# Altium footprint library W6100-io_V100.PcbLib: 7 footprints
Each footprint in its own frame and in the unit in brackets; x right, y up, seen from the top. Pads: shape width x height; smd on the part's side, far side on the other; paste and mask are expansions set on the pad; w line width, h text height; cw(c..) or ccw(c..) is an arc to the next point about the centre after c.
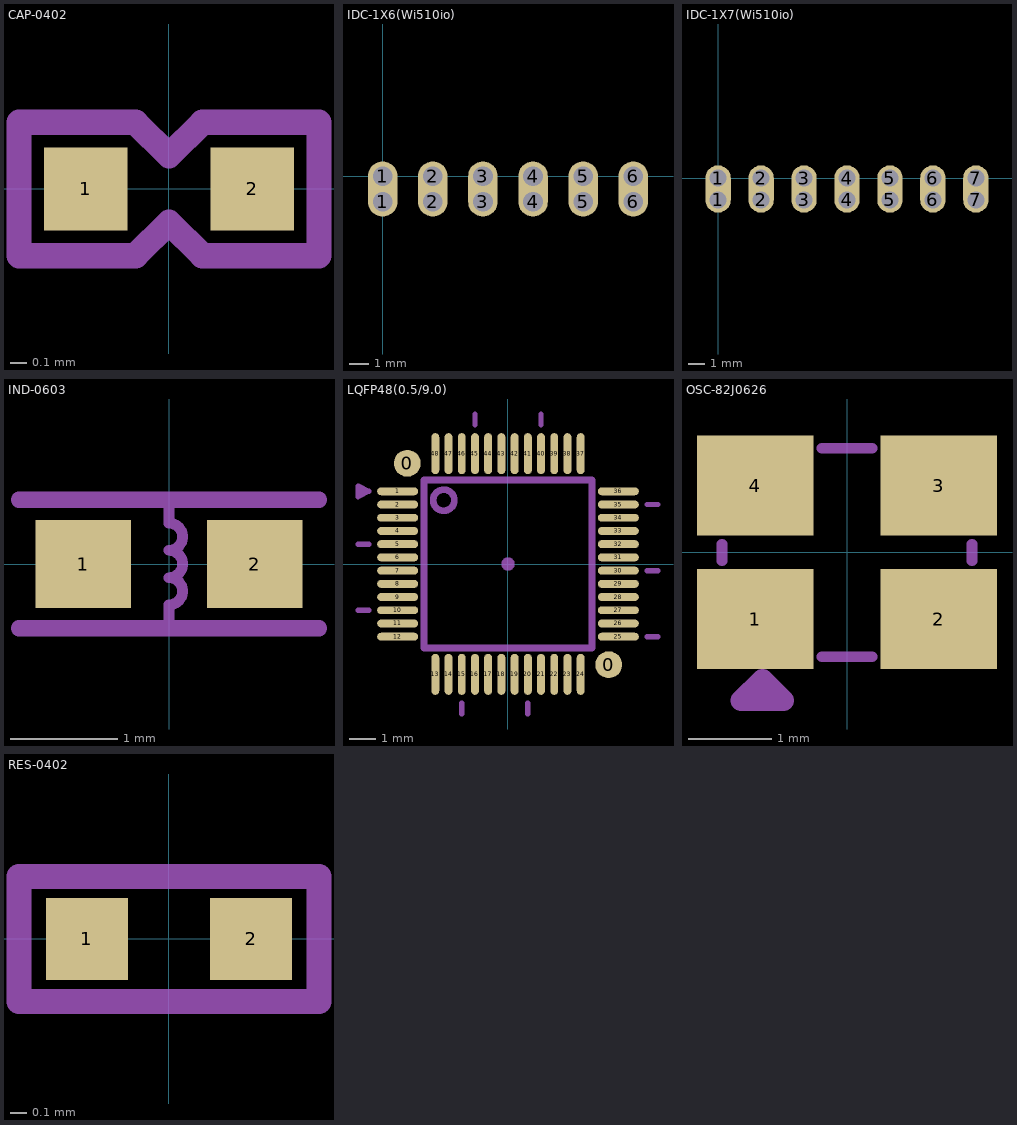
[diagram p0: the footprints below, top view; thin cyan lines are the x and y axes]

## CAP-0402 [mm]
pads (2):
  rect 0.5x0.5 smd: 1(-0.5,0) 2(0.5,0)
Mechanical 3:
  lines w0.152: -0.9,-0.4 -0.2,-0.4 0,-0.2 0.2,-0.4 0.9,-0.4 0.9,0.4 0.2,0.4 0,0.2 -0.2,0.4 -0.9,0.4 -0.9,-0.4
3D body "CAPC1005X06.STEP": height 0.6, standoff 0, extent -0.483,-0.254 0.517,0.246

## IDC-1X6(Wi510io) [mm]
pads (12):
  oval 1.5x2.5 hole 1 copper offset 0,0.5: 1(0,-1.3) 2(2.54,-1.3) 3(5.08,-1.3) 4(7.62,-1.3) 5(10.16,-1.3) 6(12.7,-1.3)
  oval 1.5x2.5 hole 1 copper offset 0,-0.5: 1(0,0) 2(2.54,0) 3(5.08,0) 4(7.62,0) 5(10.16,0) 6(12.7,0)

## IDC-1X7(Wi510io) [mm]
pads (14):
  oval 1.5x2.5 hole 1 copper offset 0,0.5: 1(0,-1.3) 2(2.54,-1.3) 3(5.08,-1.3) 4(7.62,-1.3) 5(10.16,-1.3) 6(12.7,-1.3) 7(15.24,-1.3)
  oval 1.5x2.5 hole 1 copper offset 0,-0.5: 1(0,0) 2(2.54,0) 3(5.08,0) 4(7.62,0) 5(10.16,0) 6(12.7,0) 7(15.24,0)

## IND-0603 [mm] "Inductor 0603(1608)"
pads (2):
  rect 0.89x0.82 smd: 1(-0.8,0) 2(0.8,0)
Mechanical 3:
  lines w0.1: 0,-0.6 0,-0.381 ccw(c0,-0.254) 0,-0.127 ccw(c0,0) 0,0.127 ccw(c0,0.254) 0,0.381 0,0.6
  lines w0.152: -1.4,-0.6 1.4,-0.6 ; -1.4,0.6 1.4,0.6
3D body "User Library-Chip InductorINDC1608X95N.STEP": height 0.95, standoff 0, extent -0.8,-0.4 0.8,0.4

## LQFP48(0.5/9.0) [mm]
pads (50):
  round 1.016 smd: 0(-3.81,3.81) 0(3.81,-3.81)
  oval 1.55x0.3 smd: 1(-4.175,2.75) 2(-4.175,2.25) 3(-4.175,1.75) 4(-4.175,1.25) 5(-4.175,0.75) 6(-4.175,0.25) 7(-4.175,-0.25) 8(-4.175,-0.75) 9(-4.175,-1.25) 10(-4.175,-1.75) 11(-4.175,-2.25) 12(-4.175,-2.75) 25(4.175,-2.75) 26(4.175,-2.25) 27(4.175,-1.75) 28(4.175,-1.25) 29(4.175,-0.75) 30(4.175,-0.25) 31(4.175,0.25) 32(4.175,0.75) 33(4.175,1.25) 34(4.175,1.75) 35(4.175,2.25) 36(4.175,2.75)
  oval 0.3x1.55 smd: 13(-2.75,-4.175) 14(-2.25,-4.175) 15(-1.75,-4.175) 16(-1.25,-4.175) 17(-0.75,-4.175) 18(-0.25,-4.175) 19(0.25,-4.175) 20(0.75,-4.175) 21(1.25,-4.175) 22(1.75,-4.175) 23(2.25,-4.175) 24(2.75,-4.175) 37(2.75,4.175) 38(2.25,4.175) 39(1.75,4.175) 40(1.25,4.175) 41(0.75,4.175) 42(0.25,4.175) 43(-0.25,4.175) 44(-0.75,4.175) 45(-1.25,4.175) 46(-1.75,4.175) 47(-2.25,4.175) 48(-2.75,4.175)
Mechanical 3:
  circle w0.254: c0,0 r0.127
  circle w0.254: c-2.432,2.413 r0.4
  lines w0.203: -5.675,-1.75 -5.275,-1.75 ; -5.675,0.75 -5.275,0.75 ; -5.675,2.75 -5.275,2.75 ; -1.75,-5.675 -1.75,-5.275 ; -1.25,5.275 -1.25,5.675 ; 0.75,-5.675 0.75,-5.275 ; 1.25,5.275 1.25,5.675 ; 5.275,-2.75 5.675,-2.75 ; 5.275,-0.25 5.675,-0.25 ; 5.275,2.25 5.675,2.25 ; -5.275,2.75 -5.675,2.95 -5.675,2.55 -5.275,2.75
  lines w0.254: -3.175,-3.175 3.175,-3.175 3.175,3.175 -3.175,3.175 -3.175,-3.175
3D body "User Library-lqfp48-1.STEP": height 1.5, standoff 0.02, extent -4.5,-4.5 4.5,4.5

## OSC-82J0626 [mm]
pads (4):
  rect 1.4x1.2 smd: 1(-1.1,-0.8) 2(1.1,-0.8) 3(1.1,0.8) 4(-1.1,0.8)
Mechanical 3:
  lines w0.127: -1.5,-0.1 -1.5,0.1 ; -0.3,-1.25 0.3,-1.25 ; -0.3,1.25 0.3,1.25 ; 1.5,-0.1 1.5,0.1
  lines w0.254: -1.27,-1.778 -1.016,-1.524 -0.762,-1.778 -1.27,-1.778
3D body "User Library-ABRACON_ASE.STEP": height 1.06, standoff 0.02, extent -1.7,-1.35 1.7,1.35

## RES-0402 [mm]
pads (2):
  rect 0.5x0.5 smd: 1(-0.5,0) 2(0.5,0)
Mechanical 3:
  lines w0.152: -0.914,-0.381 0.914,-0.381 0.914,0.381 -0.914,0.381 -0.914,-0.381
3D body "RES_C1005X04N.STEP": height 0.35, standoff 0, extent -0.5,-0.254 0.5,0.246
